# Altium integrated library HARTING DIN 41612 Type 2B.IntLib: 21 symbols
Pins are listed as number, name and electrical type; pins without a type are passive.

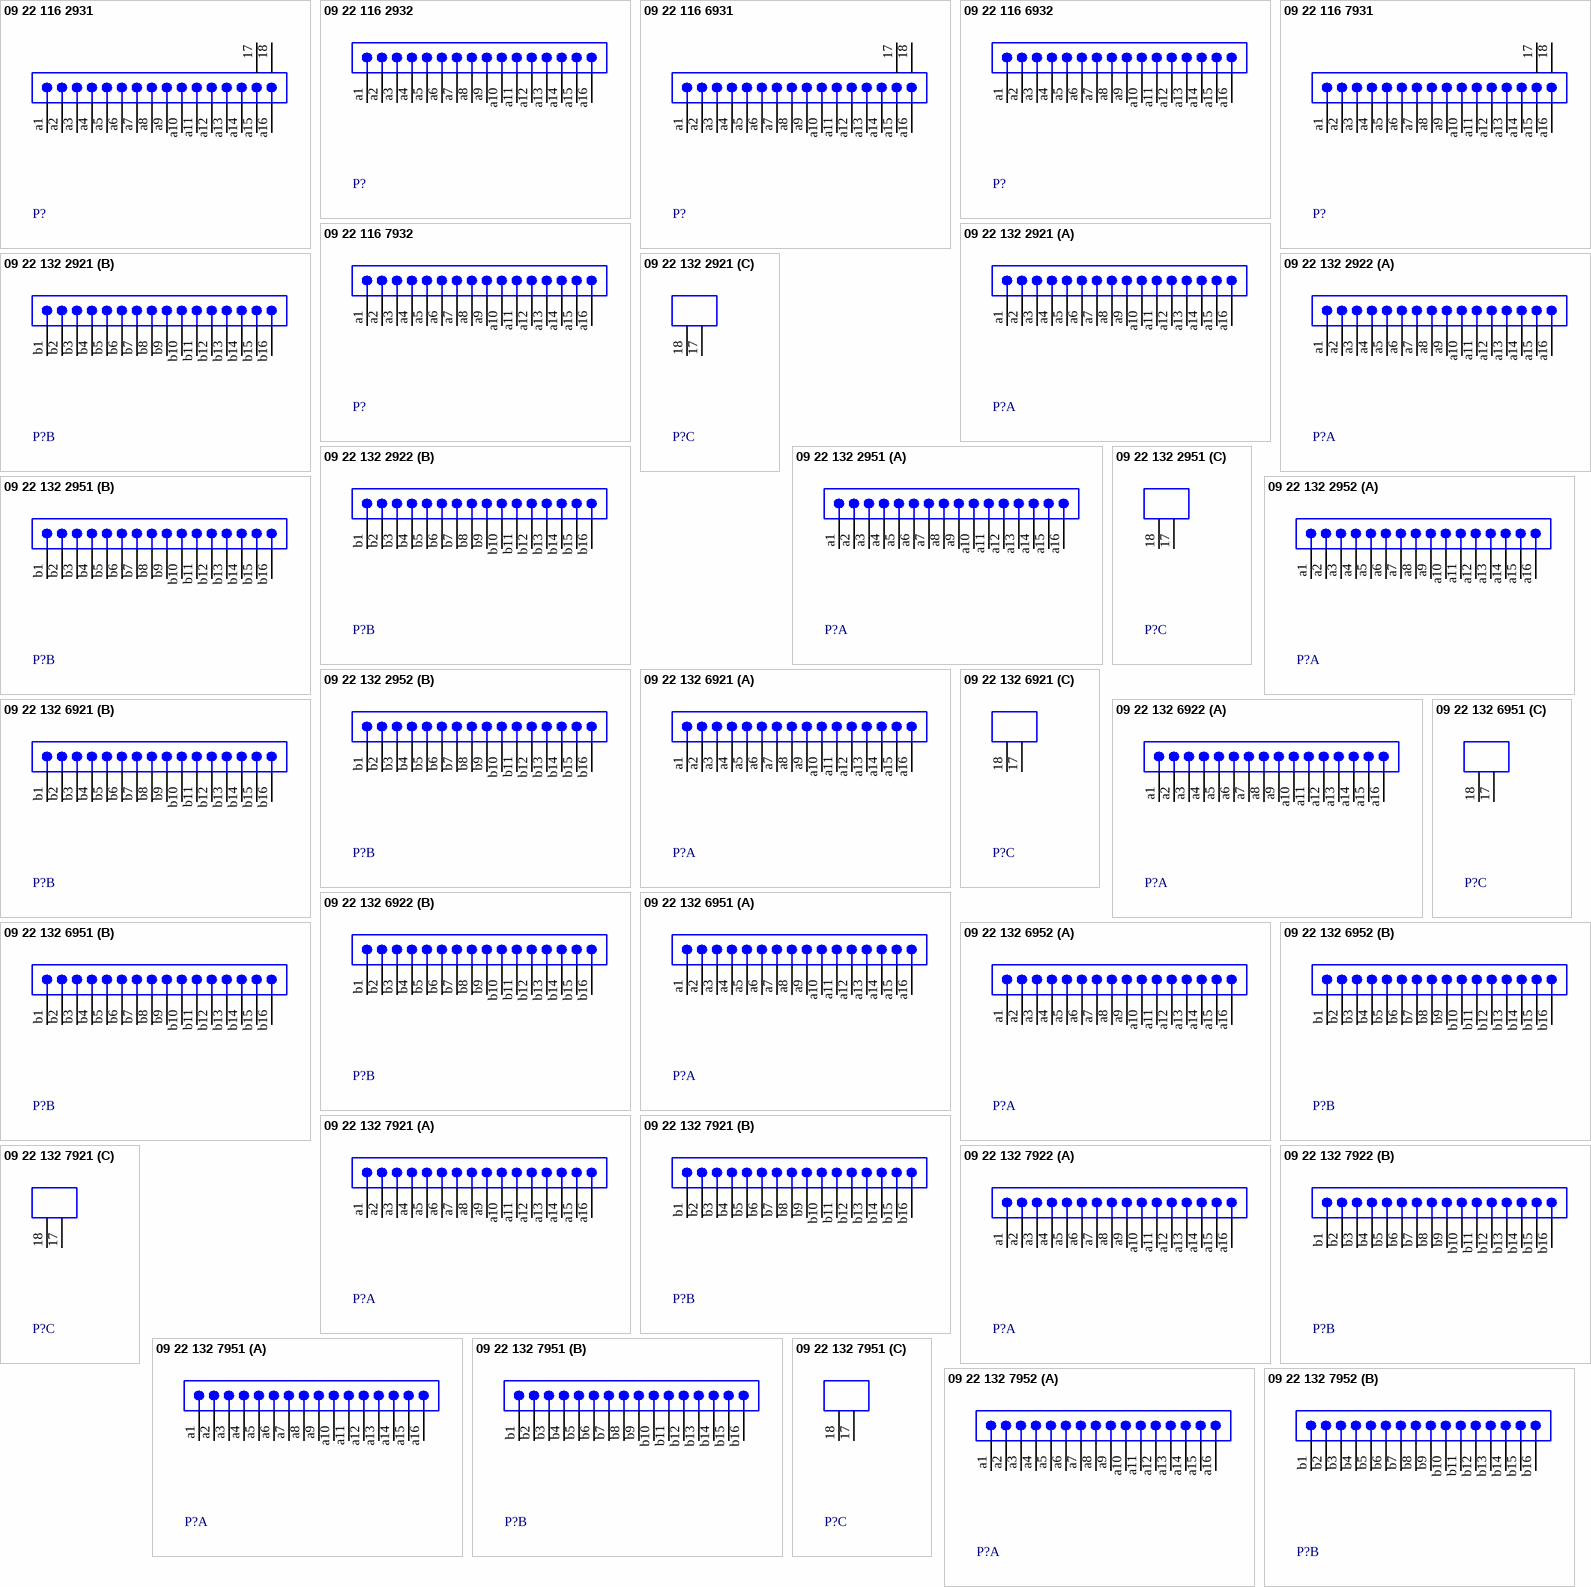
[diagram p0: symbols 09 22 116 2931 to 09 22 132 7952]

## 09 22 116 2931
designator P?
Eurocard DIN 41612, Type 2B, Half Size, 16 Position, Row a, Performance level 1, Male, Lead 3.0 mm, Pitch 2.54 mm; DrillSize: Corresponds to nominal value.
footprint 0922116x931 (Connector; DIN 41612, Type 2B, Thru-Hole; Row a, 16 Position; Right Angle)
signal-integrity model DIN 41612
pins: 17 MH1 "Mounting Fixture", 18 MH2 "Mounting Fixture", a1, a2, a3, a4, a5, a6, a7, a8, a9, a10, a11, a12, a13, a14, a15, a16

## 09 22 116 2932
designator P?
Eurocard DIN 41612, Type 2B, Half Size, 16 Position, Row a, Performance level 1, Male, Lead 3.0 mm, Pitch 2.54 mm; DrillSize: Corresponds to nominal value.
footprint 0922116x932 (Connector; DIN 41612, Type 2B, Thru-Hole; Row a, 16 Position; Vertical, No Mounting Fixture)
signal-integrity model DIN 41612
pins: a1, a2, a3, a4, a5, a6, a7, a8, a9, a10, a11, a12, a13, a14, a15, a16

## 09 22 116 6931
designator P?
Eurocard DIN 41612, Type 2B, Half Size, 16 Position, Row a, Performance level 2, Male, Lead 3.0 mm, Pitch 2.54 mm; DrillSize: Corresponds to nominal value.
footprint 0922116x931 (Connector; DIN 41612, Type 2B, Thru-Hole; Row a, 16 Position; Right Angle)
signal-integrity model DIN 41612
pins: 17 MH1 "Mounting Fixture", 18 MH2 "Mounting Fixture", a1, a2, a3, a4, a5, a6, a7, a8, a9, a10, a11, a12, a13, a14, a15, a16

## 09 22 116 6932
designator P?
Eurocard DIN 41612, Type 2B, Half Size, 16 Position, Row a, Performance level 2, Male, Lead 3.0 mm, Pitch 2.54 mm; DrillSize: Corresponds to nominal value.
footprint 0922116x932 (Connector; DIN 41612, Type 2B, Thru-Hole; Row a, 16 Position; Vertical, No Mounting Fixture)
signal-integrity model DIN 41612
pins: a1, a2, a3, a4, a5, a6, a7, a8, a9, a10, a11, a12, a13, a14, a15, a16

## 09 22 116 7931
designator P?
Eurocard DIN 41612, Type 2B, Half Size, 16 Position, Row a, Performance level 3, Male, Lead 3.0 mm, Pitch 2.54 mm; DrillSize: Corresponds to nominal value.
footprint 0922116x931 (Connector; DIN 41612, Type 2B, Thru-Hole; Row a, 16 Position; Right Angle)
signal-integrity model DIN 41612
pins: 17 MH1 "Mounting Fixture", 18 MH2 "Mounting Fixture", a1, a2, a3, a4, a5, a6, a7, a8, a9, a10, a11, a12, a13, a14, a15, a16

## 09 22 116 7932
designator P?
Eurocard DIN 41612, Type 2B, Half Size, 16 Position, Row a, Performance level 3, Male, Lead 3.0 mm, Pitch 2.54 mm; DrillSize: Corresponds to nominal value.
footprint 0922116x932 (Connector; DIN 41612, Type 2B, Thru-Hole; Row a, 16 Position; Vertical, No Mounting Fixture)
signal-integrity model DIN 41612
pins: a1, a2, a3, a4, a5, a6, a7, a8, a9, a10, a11, a12, a13, a14, a15, a16

## 09 22 132 2921
designator P?
Eurocard DIN 41612, Type 2B, Half Size, 32 Position, Rows a+b, Performance level 1, Male, Lead 3.0 mm, Pitch 2.54 mm; DrillSize: Corresponds to nominal value.
footprint 0922132x921 (Connector; DIN 41612, Type 2B, Thru-Hole; Rows a+b, 32 Position; Right Angle)
signal-integrity model DIN 41612
part A pins: a1, a2, a3, a4, a5, a6, a7, a8, a9, a10, a11, a12, a13, a14, a15, a16
part B pins: b1, b2, b3, b4, b5, b6, b7, b8, b9, b10, b11, b12, b13, b14, b15, b16
part C pins: 17 MH1 "Mounting Fixture", 18 MH2 "Mounting Fixture"

## 09 22 132 2922
designator P?
Eurocard DIN 41612, Type 2B, Half Size, 32 Position, Rows a+b, Performance level 1, Male, Lead 3.0 mm, Pitch 2.54 mm; DrillSize: Corresponds to nominal value.
footprint 0922132x922 (Connector; DIN 41612, Type 2B, Thru-Hole; Rows a+b, 32 Position; Vertical, No Mounting Fixture)
signal-integrity model DIN 41612
part A pins: a1, a2, a3, a4, a5, a6, a7, a8, a9, a10, a11, a12, a13, a14, a15, a16
part B pins: b1, b2, b3, b4, b5, b6, b7, b8, b9, b10, b11, b12, b13, b14, b15, b16

## 09 22 132 2951
designator P?
Eurocard DIN 41612, Type 2B, Half Size, 30+2 Position, Rows a+b, Performance level 1, Male, Lead 3.0 mm, Pitch 2.54 mm; Note: Two leading contacts at positions a1 & a16.; DrillSize: Corresponds to nominal value.
footprint 0922132x951 (Connector; DIN 41612, Type 2B, Thru-Hole; Rows a+b, 32 Position; Right Angle)
signal-integrity model DIN 41612
part A pins: a1, a2, a3, a4, a5, a6, a7, a8, a9, a10, a11, a12, a13, a14, a15, a16
part B pins: b1, b2, b3, b4, b5, b6, b7, b8, b9, b10, b11, b12, b13, b14, b15, b16
part C pins: 17 MH1 "Mounting Fixture", 18 MH2 "Mounting Fixture"

## 09 22 132 2952
designator P?
Eurocard DIN 41612, Type 2B, Half Size, 30+2 Position, Rows a+b, Performance level 1, Male, Lead 3.0 mm, Pitch 2.54 mm; Note: Two leading contacts at positions a1 & a16.; DrillSize: Corresponds to nominal value.
footprint 922132x952 (Connector; DIN 41612, Type 2B, Thru-Hole; Rows a+b, 32 Position; Vertical)
signal-integrity model DIN 41612
part A pins: a1, a2, a3, a4, a5, a6, a7, a8, a9, a10, a11, a12, a13, a14, a15, a16
part B pins: b1, b2, b3, b4, b5, b6, b7, b8, b9, b10, b11, b12, b13, b14, b15, b16

## 09 22 132 6921
designator P?
Eurocard DIN 41612, Type 2B, Half Size, 32 Position, Rows a+b, Performance level 2, Male, Lead 3.0 mm, Pitch 2.54 mm; DrillSize: Corresponds to nominal value.
footprint 0922132x921 (Connector; DIN 41612, Type 2B, Thru-Hole; Rows a+b, 32 Position; Right Angle)
signal-integrity model DIN 41612
part A pins: a1, a2, a3, a4, a5, a6, a7, a8, a9, a10, a11, a12, a13, a14, a15, a16
part B pins: b1, b2, b3, b4, b5, b6, b7, b8, b9, b10, b11, b12, b13, b14, b15, b16
part C pins: 17 MH1 "Mounting Fixture", 18 MH2 "Mounting Fixture"

## 09 22 132 6922
designator P?
Eurocard DIN 41612, Type 2B, Half Size, 32 Position, Rows a+b, Performance level 2, Male, Lead 3.0 mm, Pitch 2.54 mm; DrillSize: Corresponds to nominal value.
footprint 0922132x922 (Connector; DIN 41612, Type 2B, Thru-Hole; Rows a+b, 32 Position; Vertical, No Mounting Fixture)
signal-integrity model DIN 41612
part A pins: a1, a2, a3, a4, a5, a6, a7, a8, a9, a10, a11, a12, a13, a14, a15, a16
part B pins: b1, b2, b3, b4, b5, b6, b7, b8, b9, b10, b11, b12, b13, b14, b15, b16

## 09 22 132 6951
designator P?
Eurocard DIN 41612, Type 2B, Half Size, 30+2 Position, Rows a+b, Performance level 2, Male, Lead 3.0 mm, Pitch 2.54 mm; Note: Two leading contacts at positions a1 & a16.; DrillSize: Corresponds to nominal value.
footprint 0922132x951 (Connector; DIN 41612, Type 2B, Thru-Hole; Rows a+b, 32 Position; Right Angle)
signal-integrity model DIN 41612
part A pins: a1, a2, a3, a4, a5, a6, a7, a8, a9, a10, a11, a12, a13, a14, a15, a16
part B pins: b1, b2, b3, b4, b5, b6, b7, b8, b9, b10, b11, b12, b13, b14, b15, b16
part C pins: 17 MH1 "Mounting Fixture", 18 MH2 "Mounting Fixture"

## 09 22 132 6952
designator P?
Eurocard DIN 41612, Type 2B, Half Size, 30+2 Position, Rows a+b, Performance level 2, Male, Lead 3.0 mm, Pitch 2.54 mm; Note: Two leading contacts at positions a1 & a16.; DrillSize: Corresponds to nominal value.
footprint 922132x952 (Connector; DIN 41612, Type 2B, Thru-Hole; Rows a+b, 32 Position; Vertical)
signal-integrity model DIN 41612
part A pins: a1, a2, a3, a4, a5, a6, a7, a8, a9, a10, a11, a12, a13, a14, a15, a16
part B pins: b1, b2, b3, b4, b5, b6, b7, b8, b9, b10, b11, b12, b13, b14, b15, b16

## 09 22 132 7921
designator P?
Eurocard DIN 41612, Type 2B, Half Size, 32 Position, Rows a+b, Performance level 3, Male, Lead 3.0 mm, Pitch 2.54 mm; DrillSize: Corresponds to nominal value.
footprint 0922132x921 (Connector; DIN 41612, Type 2B, Thru-Hole; Rows a+b, 32 Position; Right Angle)
signal-integrity model DIN 41612
part A pins: a1, a2, a3, a4, a5, a6, a7, a8, a9, a10, a11, a12, a13, a14, a15, a16
part B pins: b1, b2, b3, b4, b5, b6, b7, b8, b9, b10, b11, b12, b13, b14, b15, b16
part C pins: 17 MH1 "Mounting Fixture", 18 MH2 "Mounting Fixture"

## 09 22 132 7922
designator P?
Eurocard DIN 41612, Type 2B, Half Size, 32 Position, Rows a+b, Performance level 3, Male, Lead 3.0 mm, Pitch 2.54 mm; DrillSize: Corresponds to nominal value.
footprint 0922132x922 (Connector; DIN 41612, Type 2B, Thru-Hole; Rows a+b, 32 Position; Vertical, No Mounting Fixture)
signal-integrity model DIN 41612
part A pins: a1, a2, a3, a4, a5, a6, a7, a8, a9, a10, a11, a12, a13, a14, a15, a16
part B pins: b1, b2, b3, b4, b5, b6, b7, b8, b9, b10, b11, b12, b13, b14, b15, b16

## 09 22 132 7951
designator P?
Eurocard DIN 41612, Type 2B, Half Size, 30+2 Position, Rows a+b, Performance level 3, Male, Lead 3.0 mm, Pitch 2.54 mm; Note: Two leading contacts at positions a1 & a16.; DrillSize: Corresponds to nominal value.
footprint 0922132x951 (Connector; DIN 41612, Type 2B, Thru-Hole; Rows a+b, 32 Position; Right Angle)
signal-integrity model DIN 41612
part A pins: a1, a2, a3, a4, a5, a6, a7, a8, a9, a10, a11, a12, a13, a14, a15, a16
part B pins: b1, b2, b3, b4, b5, b6, b7, b8, b9, b10, b11, b12, b13, b14, b15, b16
part C pins: 17 MH1 "Mounting Fixture", 18 MH2 "Mounting Fixture"

## 09 22 132 7952
designator P?
Eurocard DIN 41612, Type 2B, Half Size, 30+2 Position, Rows a+b, Performance level 3, Male, Lead 3.0 mm, Pitch 2.54 mm; Note: Two leading contacts at positions a1 & a16.; DrillSize: Corresponds to nominal value.
footprint 922132x952 (Connector; DIN 41612, Type 2B, Thru-Hole; Rows a+b, 32 Position; Vertical)
signal-integrity model DIN 41612
part A pins: a1, a2, a3, a4, a5, a6, a7, a8, a9, a10, a11, a12, a13, a14, a15, a16
part B pins: b1, b2, b3, b4, b5, b6, b7, b8, b9, b10, b11, b12, b13, b14, b15, b16

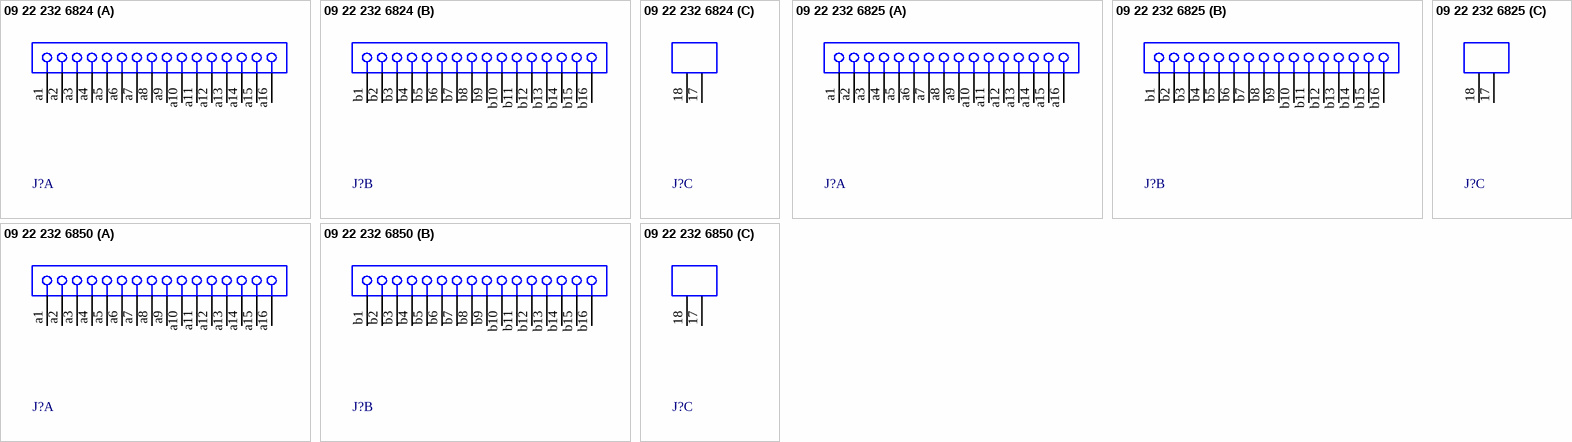
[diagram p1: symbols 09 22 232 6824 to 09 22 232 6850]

## 09 22 232 6824
designator J?
Eurocard DIN 41612, Type 2B, Half Size, 32 Position, Rows a+b, Performance level 2, Female, Lead 2.9 mm, Pitch 2.54 mm; DrillSize: Corresponds to nominal value.
footprint 0922232x824 (Connector; DIN 41612, Type 2B, Thru-Hole; Rows a+b, 32 Position; Vertical)
signal-integrity model DIN 41612
part A pins: a1, a2, a3, a4, a5, a6, a7, a8, a9, a10, a11, a12, a13, a14, a15, a16
part B pins: b1, b2, b3, b4, b5, b6, b7, b8, b9, b10, b11, b12, b13, b14, b15, b16
part C pins: 17 MH1 "Mounting Fixture", 18 MH2 "Mounting Fixture"

## 09 22 232 6825
designator J?
Eurocard DIN 41612, Type 2B, Half Size, 32 Position, Rows a+b, Performance level 2, Female, Lead 4.5 mm, Pitch 2.54 mm; DrillSize: Corresponds to nominal value.
footprint 0922232x825 (Connector; DIN 41612, Type 2B, Thru-Hole; Rows a+b, 32 Position; Vertical)
signal-integrity model DIN 41612
part A pins: a1, a2, a3, a4, a5, a6, a7, a8, a9, a10, a11, a12, a13, a14, a15, a16
part B pins: b1, b2, b3, b4, b5, b6, b7, b8, b9, b10, b11, b12, b13, b14, b15, b16
part C pins: 17 MH1 "Mounting Fixture", 18 MH2 "Mounting Fixture"

## 09 22 232 6850
designator J?
Eurocard DIN 41612, Type 2B, Half Size, 32 Position, Rows a+b, Performance level 2, Female, Lead 4.5 mm, Pitch 2.54 mm; DrillSize: Corresponds to nominal value.
footprint 0922232x850 (Connector; DIN 41612, Type 2B, Thru-Hole; Rows a+b, 32 Position; Vertical)
signal-integrity model DIN 41612
part A pins: a1, a2, a3, a4, a5, a6, a7, a8, a9, a10, a11, a12, a13, a14, a15, a16
part B pins: b1, b2, b3, b4, b5, b6, b7, b8, b9, b10, b11, b12, b13, b14, b15, b16
part C pins: 17 MH1 "Mounting Fixture", 18 MH2 "Mounting Fixture"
